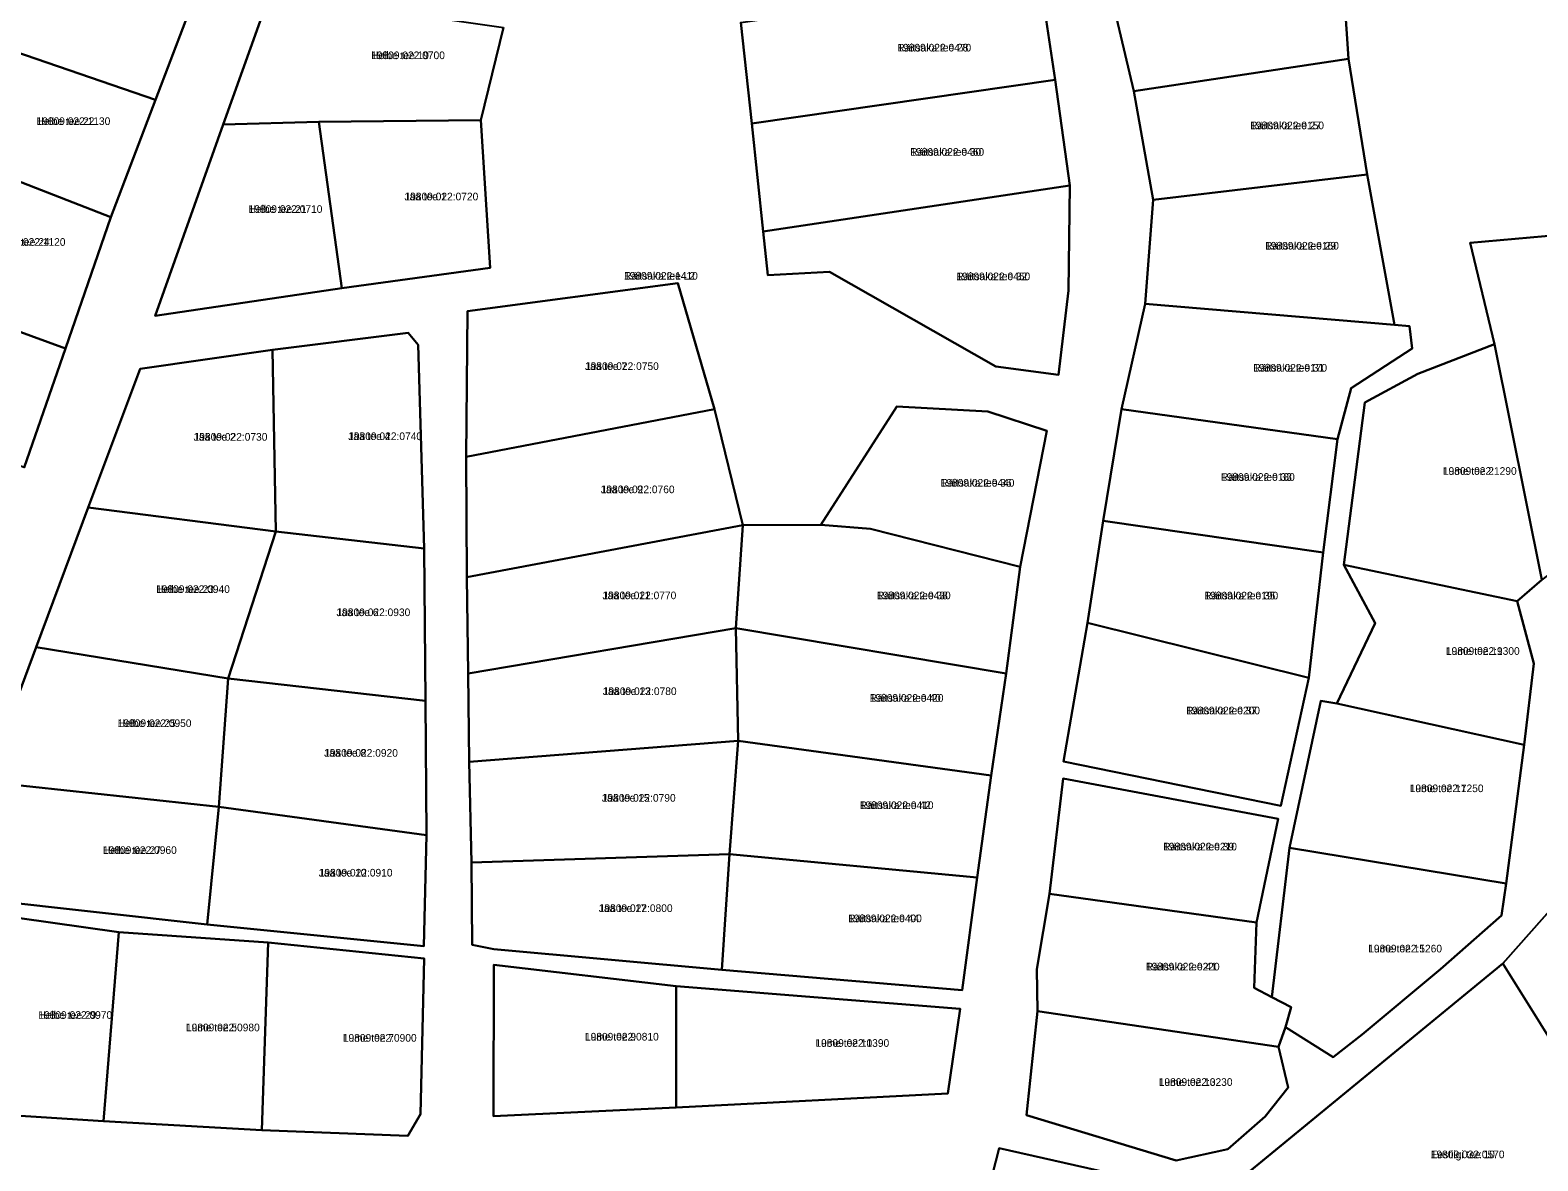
# Model space of a CAD drawing. Extents: x 516875 to 535633, y 6574491 to 6593094.
# Drawn here: x 521072.3 to 521368.5, y 6588617.1 to 6588839.3 of the extents above; entities that cross this region are included whole.
import ezdxf

# ---------------------------------------------------------------- set-up
doc = ezdxf.new("R2010")
doc.units = 0
for name, color, linetype in [('L_AADRESS', 7, 'Continuous'), ('PIIR', 7, 'Continuous'), ('TUNNUS', 7, 'Continuous')]:
    doc.layers.add(name, color=color, linetype=linetype)

msp = doc.modelspace()

# ---------------------------------------------------------------- linework, layer by layer
at = {"layer": 'PIIR'}
for points in [[(521105.75, 6588848.88), (521096.91, 6588825.62), (521058.55, 6588838.76), (521067.86, 6588862.57)], [(521329.66, 6588858.17), (521331.31, 6588833.69), (521289.1, 6588827.33), (521283.4, 6588851.45)], [(521214.04, 6588820.93), (521211.9, 6588840.81), (521270.72, 6588849.28), (521273.65, 6588829.51)], [(521165.27, 6588839.84), (521160.8, 6588821.6), (521128.99, 6588821.3), (521110.21, 6588820.78), (521119.35, 6588846.44)], [(521096.91, 6588825.62), (521088.13, 6588802.57), (521050.74, 6588817.12), (521058.55, 6588838.76)], [(521331.31, 6588833.69), (521334.98, 6588810.95), (521292.9, 6588805.96), (521289.1, 6588827.33)], [(521216.28, 6588799.74), (521214.04, 6588820.93), (521273.65, 6588829.51), (521276.54, 6588808.75)], [(521128.99, 6588821.3), (521133.52, 6588788.59), (521096.85, 6588783.16), (521110.21, 6588820.78)], [(521133.52, 6588788.59), (521128.99, 6588821.3), (521160.8, 6588821.6), (521162.66, 6588792.57)], [(521088.13, 6588802.57), (521079.2, 6588776.74), (521040.94, 6588790.72), (521050.74, 6588817.12)], [(521334.98, 6588810.95), (521340.36, 6588781.42), (521291.36, 6588785.5), (521292.9, 6588805.96)], [(521274.35, 6588771.59), (521262, 6588773.19), (521229.31, 6588791.83), (521217.21, 6588791.18), (521216.28, 6588799.74), (521276.54, 6588808.75), (521276.27, 6588788.14)], [(521372.37, 6588733.63), (521369.27, 6588731.29), (521359.98, 6588777.57), (521355.22, 6588797.52), (521393.53, 6588800.89), (521397.43, 6588767.88), (521406.4, 6588749.3), (521386.6, 6588739.78)], [(521079.2, 6588776.74), (521071.09, 6588753.38), (521032.53, 6588767.91), (521040.94, 6588790.72)], [(521206.73, 6588764.84), (521157.97, 6588755.47), (521158.18, 6588784.1), (521199.52, 6588789.59)], [(521206.73, 6588764.84), (521199.52, 6588789.59), (521158.18, 6588784.1), (521157.97, 6588755.47), (521158.06, 6588731.8), (521158.34, 6588712.9), (521158.55, 6588695.52), (521158.98, 6588675.74), (521159.12, 6588659.61), (521163.35, 6588658.74), (521208.17, 6588654.66), (521255.39, 6588650.66), (521258.33, 6588672.82), (521261.09, 6588692.87), (521264.06, 6588712.86), (521266.77, 6588733.87), (521272.04, 6588760.6), (521260.42, 6588764.35), (521242.57, 6588765.35), (521227.65, 6588742.09), (521212.32, 6588742.07)], [(521286.7, 6588764.8), (521291.36, 6588785.5), (521340.36, 6588781.42), (521343.29, 6588781.15), (521343.84, 6588776.78), (521331.85, 6588768.97), (521329.17, 6588758.92)], [(521063.47, 6588668.41), (521107.05, 6588663.6), (521149.65, 6588659.31), (521150.16, 6588681.16), (521149.94, 6588707.53), (521149.67, 6588737.45), (521148.53, 6588777.45), (521146.57, 6588779.85), (521119.86, 6588776.48), (521093.88, 6588772.73), (521083.67, 6588745.51), (521073.45, 6588718.07), (521069.12, 6588706.44), (521066.72, 6588691.27)], [(521120.53, 6588740.8), (521119.86, 6588776.48), (521146.57, 6588779.85), (521148.53, 6588777.45), (521149.67, 6588737.45)], [(521344.94, 6588771.8), (521359.98, 6588777.57), (521369.27, 6588731.29), (521364.46, 6588727.1), (521330.42, 6588734.26), (521334.54, 6588766.11)], [(521120.53, 6588740.8), (521083.67, 6588745.51), (521093.88, 6588772.73), (521119.86, 6588776.48)], [(521158.06, 6588731.8), (521157.97, 6588755.47), (521206.73, 6588764.84), (521212.32, 6588742.07)], [(521242.57, 6588765.35), (521260.42, 6588764.35), (521272.04, 6588760.6), (521266.77, 6588733.87), (521237.36, 6588741.3), (521227.65, 6588742.09)], [(521283.08, 6588742.88), (521286.7, 6588764.8), (521329.17, 6588758.92), (521326.31, 6588736.69)], [(521120.53, 6588740.8), (521111.15, 6588711.93), (521073.45, 6588718.07), (521083.67, 6588745.51)], [(521212.32, 6588742.07), (521210.94, 6588721.8), (521158.34, 6588712.9), (521158.06, 6588731.8)], [(521237.36, 6588741.3), (521266.77, 6588733.87), (521264.06, 6588712.86), (521210.94, 6588721.8), (521212.32, 6588742.07), (521227.65, 6588742.09)], [(521326.31, 6588736.69), (521323.48, 6588712.02), (521280.02, 6588722.85), (521283.08, 6588742.88)], [(521111.15, 6588711.93), (521120.53, 6588740.8), (521149.67, 6588737.45), (521149.94, 6588707.53)], [(521364.46, 6588727.1), (521367.75, 6588714.88), (521365.85, 6588698.86), (521329.02, 6588706.98), (521336.56, 6588722.8), (521330.42, 6588734.26)], [(521413.29, 6588714.19), (521418.94, 6588723.37), (521421.81, 6588728.14), (521449.85, 6588699.7), (521477.52, 6588688.69), (521479.07, 6588668.07), (521414.43, 6588634.08), (521384.67, 6588618.99), (521384.19, 6588619.81), (521361.62, 6588655.9)], [(521210.94, 6588721.8), (521211.36, 6588699.69), (521158.55, 6588695.52), (521158.34, 6588712.9)], [(521211.36, 6588699.69), (521210.94, 6588721.8), (521264.06, 6588712.86), (521261.09, 6588692.87)], [(521323.48, 6588712.02), (521317.98, 6588686.89), (521275.29, 6588695.61), (521280.02, 6588722.85)], [(521111.15, 6588711.93), (521109.32, 6588686.7), (521066.72, 6588691.27), (521069.12, 6588706.44), (521073.45, 6588718.07)], [(521109.32, 6588686.7), (521111.15, 6588711.93), (521149.94, 6588707.53), (521150.16, 6588681.16)], [(521365.85, 6588698.86), (521362.31, 6588671.64), (521319.72, 6588678.67), (521325.84, 6588707.51), (521329.02, 6588706.98)], [(521211.36, 6588699.69), (521209.71, 6588677.4), (521158.98, 6588675.74), (521158.55, 6588695.52)], [(521211.36, 6588699.69), (521261.09, 6588692.87), (521258.33, 6588672.82), (521209.71, 6588677.4)], [(521317.49, 6588684.35), (521313.23, 6588663.98), (521272.57, 6588669.59), (521275.22, 6588692.29)], [(521066.72, 6588691.27), (521109.32, 6588686.7), (521107.05, 6588663.6), (521063.47, 6588668.41)], [(521107.05, 6588663.6), (521109.32, 6588686.7), (521150.16, 6588681.16), (521149.65, 6588659.31)], [(521209.71, 6588677.4), (521208.17, 6588654.66), (521163.35, 6588658.74), (521159.12, 6588659.61), (521158.98, 6588675.74)], [(521255.39, 6588650.66), (521208.17, 6588654.66), (521209.71, 6588677.4), (521258.33, 6588672.82)], [(521349.38, 6588654.83), (521333.96, 6588641.95), (521328.32, 6588637.5), (521318.96, 6588643.38), (521320.05, 6588647.33), (521316.22, 6588649.29), (521319.72, 6588678.67), (521362.31, 6588671.64), (521361.36, 6588665.32)], [(521270.2, 6588646.53), (521270.08, 6588654.81), (521272.57, 6588669.59), (521313.23, 6588663.98), (521312.78, 6588651.12), (521316.22, 6588649.29), (521320.05, 6588647.33), (521318.96, 6588643.38), (521317.52, 6588639.51)], [(521063.25, 6588665.81), (521089.69, 6588662.09), (521086.7, 6588624.94), (521058.07, 6588626.77)], [(521058.07, 6588626.77), (521086.7, 6588624.94), (521117.76, 6588623.14), (521146.51, 6588622.07), (521148.98, 6588626.34), (521149.66, 6588656.91), (521119.05, 6588660.07), (521089.69, 6588662.09), (521063.25, 6588665.81)], [(521089.69, 6588662.09), (521119.05, 6588660.07), (521117.76, 6588623.14), (521086.7, 6588624.94)], [(521119.05, 6588660.07), (521149.66, 6588656.91), (521148.98, 6588626.34), (521146.51, 6588622.07), (521117.76, 6588623.14)], [(521163.35, 6588655.65), (521199.23, 6588651.48), (521199.23, 6588627.59), (521163.31, 6588625.91)], [(521252.55, 6588630.39), (521255, 6588647.03), (521199.23, 6588651.48), (521163.35, 6588655.65), (521163.31, 6588625.91), (521199.23, 6588627.59)], [(521384.19, 6588619.81), (521304.11, 6588579.39), (521302.8, 6588580.8), (521290.73, 6588597.7), (521361.62, 6588655.9)], [(521199.23, 6588627.59), (521199.23, 6588651.48), (521255, 6588647.03), (521252.55, 6588630.39)], [(521314.92, 6588625.88), (521307.58, 6588619.44), (521297.42, 6588617.21), (521268.04, 6588626.12), (521270.2, 6588646.53), (521317.52, 6588639.51), (521319.46, 6588631.57)], [(521273.04, 6588580.53), (521254.42, 6588587.5), (521262.67, 6588619.64), (521305.61, 6588609.92), (521290.73, 6588597.7), (521288.62, 6588595.71)]]:
    msp.add_lwpolyline(points, close=True, dxfattribs=at)
for points in [[(521283.4, 6588851.45), (521289.1, 6588827.33), (521292.9, 6588805.96), (521291.36, 6588785.5), (521286.7, 6588764.8), (521283.08, 6588742.88), (521280.02, 6588722.85), (521275.29, 6588695.61), (521317.98, 6588686.89), (521323.48, 6588712.02), (521326.31, 6588736.69), (521329.17, 6588758.92), (521331.85, 6588768.97), (521343.84, 6588776.78), (521343.29, 6588781.15), (521340.36, 6588781.42), (521334.98, 6588810.95), (521331.31, 6588833.69), (521329.66, 6588858.17)], [(521071.09, 6588753.38), (521079.2, 6588776.74), (521088.13, 6588802.57), (521096.91, 6588825.62), (521105.75, 6588848.88)], [(521211.9, 6588840.81), (521214.04, 6588820.93), (521216.28, 6588799.74), (521217.21, 6588791.18), (521229.31, 6588791.83), (521262, 6588773.19), (521274.35, 6588771.59), (521276.27, 6588788.14), (521276.54, 6588808.75), (521273.65, 6588829.51), (521270.72, 6588849.28)], [(521119.35, 6588846.44), (521110.21, 6588820.78), (521096.85, 6588783.16), (521133.52, 6588788.59), (521162.66, 6588792.57), (521160.8, 6588821.6), (521165.27, 6588839.84)], [(521393.53, 6588800.89), (521355.22, 6588797.52), (521359.98, 6588777.57), (521344.94, 6588771.8), (521334.54, 6588766.11), (521330.42, 6588734.26), (521336.56, 6588722.8), (521329.02, 6588706.98), (521325.84, 6588707.51), (521319.72, 6588678.67), (521316.22, 6588649.29), (521312.78, 6588651.12), (521313.23, 6588663.98), (521317.49, 6588684.35), (521275.22, 6588692.29), (521272.57, 6588669.59), (521270.08, 6588654.81), (521270.2, 6588646.53), (521268.04, 6588626.12), (521297.42, 6588617.21), (521307.58, 6588619.44), (521314.92, 6588625.88), (521319.46, 6588631.57), (521317.52, 6588639.51), (521318.96, 6588643.38), (521328.32, 6588637.5), (521333.96, 6588641.95), (521349.38, 6588654.83), (521361.36, 6588665.32), (521362.31, 6588671.64), (521365.85, 6588698.86), (521367.75, 6588714.88), (521364.46, 6588727.1), (521369.27, 6588731.29)], [(521413.29, 6588714.19), (521361.62, 6588655.9), (521305.61, 6588609.92), (521262.67, 6588619.64), (521254.42, 6588587.5)]]:
    msp.add_lwpolyline(points, dxfattribs=at)

# ---------------------------------------------------------------- texts
at = {"layer": 'L_AADRESS'}
for s, p in [('Helbe tee 19', (521139.26, 6588833.61)), ('Räitsaka tee 28', (521242.67, 6588835.11)), ('Helbe tee 22', (521073.52, 6588820.67)), ('Räitsaka tee 27', (521311.99, 6588819.83)), ('Räitsaka tee 30', (521245.21, 6588814.62)), ('Jää tee 1', (521145.82, 6588805.86)), ('Helbe tee 21', (521115.19, 6588803.4)), ('Helbe tee 24', (521064.71, 6588796.93)), ('Räitsaka tee 29', (521314.92, 6588796.19)), ('Räitsaka tee L2', (521188.96, 6588790.28)), ('Räitsaka tee 32', (521254.26, 6588790.17)), ('Jää tee 7', (521181.29, 6588772.53)), ('Räitsaka tee 31', (521312.6, 6588772.21)), ('Jää tee 2', (521104.39, 6588758.64)), ('Jää tee 4', (521134.77, 6588758.76)), ('Räitsaka tee 36', (521251.17, 6588749.61)), ('Räitsaka tee 33', (521306.25, 6588750.75)), ('Lume tee 21', (521349.85, 6588751.93)), ('Jää tee 9', (521184.39, 6588748.32)), ('Helbe tee 23', (521097.01, 6588728.72)), ('Jää tee 11', (521184.73, 6588727.49)), ('Räitsaka tee 38', (521238.64, 6588727.48)), ('Räitsaka tee 35', (521302.99, 6588727.45)), ('Jää tee 6', (521132.46, 6588724.17)), ('Lume tee 19', (521350.44, 6588716.56)), ('Jää tee 13', (521184.79, 6588708.66)), ('Räitsaka tee 40', (521237.23, 6588707.34)), ('Räitsaka tee 37', (521299.41, 6588704.87)), ('Helbe tee 25', (521089.47, 6588702.38)), ('Jää tee 8', (521130.03, 6588696.54)), ('Jää tee 15', (521184.6, 6588687.71)), ('Lume tee 17', (521343.34, 6588689.58)), ('Räitsaka tee 42', (521235.27, 6588686.26)), ('Helbe tee 27', (521086.58, 6588677.44)), ('Räitsaka tee 39', (521294.88, 6588678.13)), ('Jää tee 10', (521128.97, 6588673)), ('Jää tee 17', (521184, 6588666.03)), ('Räitsaka tee 44', (521232.98, 6588664.03)), ('Lume tee 15', (521335.18, 6588658.09)), ('Räitsaka tee 41', (521291.49, 6588654.55)), ('Helbe tee 29', (521073.88, 6588645.04)), ('Lume tee 5', (521102.88, 6588642.59)), ('Lume tee 7', (521133.71, 6588640.55)), ('Lume tee 9', (521181.28, 6588640.78)), ('Lume tee 11', (521226.56, 6588639.54)), ('Lume tee 13', (521294.02, 6588631.87)), ('Eestiigi tee 10', (521347.46, 6588617.65))]:
    msp.add_text(s, height=1.5, dxfattribs=at).set_placement(p)
at = {"layer": 'TUNNUS'}
for s, p in [('19809:022:0700', (521139.26, 6588833.61)), ('19809:022:0470', (521242.67, 6588835.11)), ('19809:022:1130', (521073.52, 6588820.67)), ('19809:022:0150', (521311.99, 6588819.83)), ('19809:022:0460', (521245.21, 6588814.62)), ('19809:022:0720', (521145.82, 6588805.86)), ('19809:022:0710', (521115.19, 6588803.4)), ('19809:022:1120', (521064.71, 6588796.93)), ('19809:022:0160', (521314.92, 6588796.19)), ('19809:022:1410', (521188.96, 6588790.28)), ('19809:022:0450', (521254.26, 6588790.17)), ('19809:022:0750', (521181.29, 6588772.53)), ('19809:022:0170', (521312.6, 6588772.21)), ('19809:022:0730', (521104.39, 6588758.64)), ('19809:022:0740', (521134.77, 6588758.76)), ('19809:022:0440', (521251.17, 6588749.61)), ('19809:022:0180', (521306.25, 6588750.75)), ('19809:022:1290', (521349.85, 6588751.93)), ('19809:022:0760', (521184.39, 6588748.32)), ('19809:022:0940', (521097.01, 6588728.72)), ('19809:022:0770', (521184.73, 6588727.49)), ('19809:022:0430', (521238.64, 6588727.48)), ('19809:022:0190', (521302.99, 6588727.45)), ('19809:022:0930', (521132.46, 6588724.17)), ('19809:022:1300', (521350.44, 6588716.56)), ('19809:022:0780', (521184.79, 6588708.66)), ('19809:022:0420', (521237.23, 6588707.34)), ('19809:022:0950', (521089.47, 6588702.38)), ('19809:022:0200', (521299.41, 6588704.87)), ('19809:022:0920', (521130.03, 6588696.54)), ('19809:022:0790', (521184.6, 6588687.71)), ('19809:022:1250', (521343.34, 6588689.58)), ('19809:022:0410', (521235.27, 6588686.26)), ('19809:022:0960', (521086.58, 6588677.44)), ('19809:022:0210', (521294.88, 6588678.13)), ('19809:022:0910', (521128.97, 6588673)), ('19809:022:0800', (521184, 6588666.03)), ('19809:022:0400', (521232.98, 6588664.03)), ('19809:022:1260', (521335.18, 6588658.09)), ('19809:022:0220', (521291.49, 6588654.55)), ('19809:022:0970', (521073.88, 6588645.04)), ('19809:022:0980', (521102.88, 6588642.59)), ('19809:022:0900', (521133.71, 6588640.55)), ('19809:022:0810', (521181.28, 6588640.78)), ('19809:022:0390', (521226.56, 6588639.54)), ('19809:022:0230', (521294.02, 6588631.87)), ('19809:032:0570', (521347.46, 6588617.65))]:
    msp.add_text(s, height=1.5, dxfattribs=at).set_placement(p)

doc.saveas('drawing.dxf')
